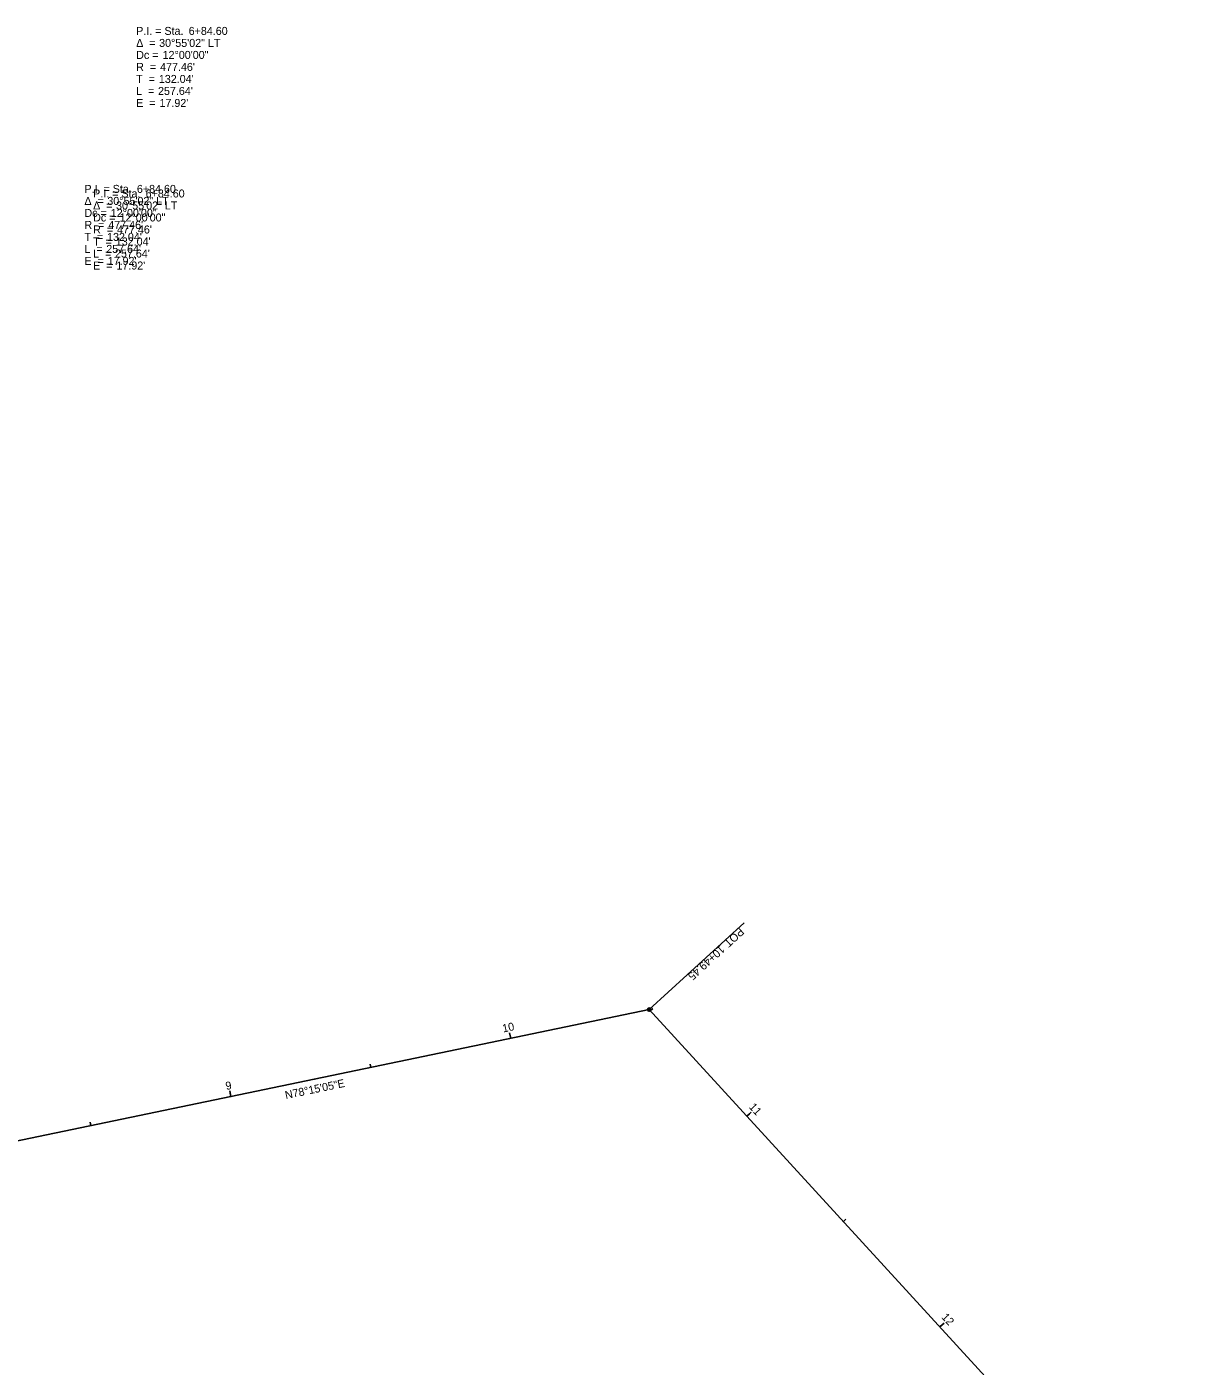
# Model space of a CAD drawing. Extents: x 2196614 to 2198263, y 660890 to 662319.
# Drawn here: x 2197020.4 to 2197426.6, y 661849.9 to 662318.5 of the extents above; entities that cross this region are included whole.
import ezdxf

# ---------------------------------------------------------------- set-up
doc = ezdxf.new("R2010")
doc.units = 0
for name, color, linetype in [('Default', 7, 'Continuous'), ('GE_X_Alignment', 7, 'Continuous'), ('GE_X_Alignment_1000_Curve_Data', 7, 'Continuous'), ('GE_X_Alignment_1000_Stations', 7, 'Continuous'), ('GE_X_Alignment_100_Curve_Data', 7, 'Continuous'), ('GE_X_Alignment_100_Stations', 7, 'Continuous'), ('GE_X_Alignment_500_Curve_Data', 7, 'Continuous'), ('GE_X_Alignment_500_Stations', 7, 'Continuous')]:
    doc.layers.add(name, color=color, linetype=linetype)

msp = doc.modelspace()

# ---------------------------------------------------------------- linework, layer by layer
at = {"layer": 'Default'}
for centre in [(2197238.07, 661974.69), (2197238.07, 661974.69), (2197238.07, 661974.69), (2197189.65, 661964.62), (2197189.65, 661964.62), (2197189.65, 661964.62), (2197120.95, 661950.33), (2197120.95, 661950.33), (2197120.95, 661950.33), (2197120.95, 661950.33), (2197120.95, 661950.33), (2197120.95, 661950.33), (2197091.75, 661944.25), (2197272.21, 661937.41), (2197339.74, 661863.66)]:
    msp.add_circle(centre, 0.0000833, dxfattribs=at)
at = {"layer": 'GE_X_Alignment'}
for p, q in [((2197003.84, 661925.97), (2197238.07, 661974.69)), ((2197238.07, 661974.69), (2197781.39, 661381.34))]:
    msp.add_line(p, q, dxfattribs=at)
at = {"layer": 'GE_X_Alignment_1000_Stations'}
for p, q in [((2197238.07, 661974.69), (2197271.26, 662005.08)), ((2197189.65, 661964.62), (2197189.25, 661966.57))]:
    msp.add_line(p, q, dxfattribs=at)
msp.add_circle((2197238.07, 661974.69), 0.6, dxfattribs=at)
at = {"layer": 'GE_X_Alignment_100_Stations'}
for p, q in [((2197238.07, 661974.69), (2197271.26, 662005.08)), ((2197238.44, 661974.28), (2197239.33, 661975.09)), ((2197189.65, 661964.62), (2197189.25, 661966.57)), ((2197140.7, 661954.43), (2197140.46, 661955.61)), ((2197091.75, 661944.25), (2197091.34, 661946.21)), ((2197272.21, 661937.41), (2197273.68, 661938.76)), ((2197042.8, 661934.07), (2197042.55, 661935.25)), ((2197305.97, 661900.53), (2197306.86, 661901.34)), ((2197339.74, 661863.66), (2197341.22, 661865.01))]:
    msp.add_line(p, q, dxfattribs=at)
msp.add_circle((2197238.07, 661974.69), 0.6, dxfattribs=at)
at = {"layer": 'GE_X_Alignment_500_Stations'}
for p, q in [((2197238.07, 661974.69), (2197271.26, 662005.08)), ((2197189.65, 661964.62), (2197189.25, 661966.57)), ((2197091.75, 661944.25), (2197091.51, 661945.43)), ((2197272.21, 661937.41), (2197273.09, 661938.22)), ((2197339.74, 661863.66), (2197340.63, 661864.47))]:
    msp.add_line(p, q, dxfattribs=at)
msp.add_circle((2197238.07, 661974.69), 0.6, dxfattribs=at)

# ---------------------------------------------------------------- texts
at = {"layer": 'GE_X_Alignment_1000_Curve_Data'}
for s, p in [('P.I. = Sta. ', (2197058.62, 662315.66)), ('6+84.60', (2197076.98, 662315.66)), ('Δ  = ', (2197058.62, 662311.46)), ('30°55\'02" LT', (2197066.64, 662311.46)), ('Dc = ', (2197058.62, 662307.26)), ('12°00\'00"', (2197067.86, 662307.26)), ('R  = ', (2197058.62, 662303.06)), ("132.04'", (2197066.55, 662298.86)), ("477.46'", (2197066.98, 662303.06)), ('T  = ', (2197058.62, 662298.86)), ('L  = ', (2197058.62, 662294.66)), ("257.64'", (2197066.26, 662294.66)), ('E  = ', (2197058.62, 662290.46)), ("17.92'", (2197066.77, 662290.46))]:
    msp.add_text(s, height=2.8, dxfattribs=at).set_placement(p)
at = {"layer": 'GE_X_Alignment_1000_Stations'}
for s, rotation, p in [('POT', 222.4797, (2197269.67, 662003.56)), ('10+49.45', 222.4797, (2197262.94, 661997.39)), ('10', 11.7486, (2197186.99, 661966.66)), ('N78°15\'05"E', 11.7486, (2197110.98, 661943.35))]:
    msp.add_text(s, height=2.8, rotation=rotation, dxfattribs=at).set_placement(p)
at = {"layer": 'GE_X_Alignment_100_Curve_Data'}
for s, p in [('P.I. = Sta. ', (2197040.51, 662260.39)), ('6+84.60', (2197058.87, 662260.39)), ('Δ  = ', (2197040.51, 662256.19)), ('30°55\'02" LT', (2197048.53, 662256.19)), ('Dc = ', (2197040.51, 662251.99)), ('R  = ', (2197040.51, 662247.79)), ("477.46'", (2197048.87, 662247.79)), ('12°00\'00"', (2197049.74, 662251.99)), ('T  = ', (2197040.51, 662243.59)), ("132.04'", (2197048.44, 662243.59)), ('L  = ', (2197040.51, 662239.39)), ("257.64'", (2197048.15, 662239.39)), ('E  = ', (2197040.51, 662235.19)), ("17.92'", (2197048.66, 662235.19))]:
    msp.add_text(s, height=2.8, dxfattribs=at).set_placement(p)
at = {"layer": 'GE_X_Alignment_100_Stations'}
for s, rotation, p in [('POT', 222.4797, (2197269.67, 662003.56)), ('10+49.45', 222.4797, (2197262.94, 661997.39)), ('10', 11.7486, (2197186.99, 661966.66)), ('N78°15\'05"E', 11.7486, (2197110.98, 661943.35)), ('9', 11.7486, (2197090.18, 661946.53)), ('11', 312.4797, (2197272.78, 661940.48)), ('12', 312.4797, (2197340.11, 661866.96))]:
    msp.add_text(s, height=2.8, rotation=rotation, dxfattribs=at).set_placement(p)
at = {"layer": 'GE_X_Alignment_500_Curve_Data'}
for s, p in [('P.I. = Sta. ', (2197043.56, 662258.79)), ('6+84.60', (2197061.93, 662258.79)), ('Δ  = ', (2197043.56, 662254.59)), ('30°55\'02" LT', (2197051.58, 662254.59)), ('Dc = ', (2197043.56, 662250.39)), ('12°00\'00"', (2197052.8, 662250.39)), ('R  = ', (2197043.56, 662246.19)), ("477.46'", (2197051.93, 662246.19)), ('T  = ', (2197043.56, 662241.99)), ("132.04'", (2197051.49, 662241.99)), ('L  = ', (2197043.56, 662237.79)), ('E  = ', (2197043.56, 662233.59)), ("257.64'", (2197051.21, 662237.79)), ("17.92'", (2197051.71, 662233.59))]:
    msp.add_text(s, height=2.8, dxfattribs=at).set_placement(p)
at = {"layer": 'GE_X_Alignment_500_Stations'}
for s, rotation, p in [('POT', 222.4797, (2197269.67, 662003.56)), ('10+49.45', 222.4797, (2197262.94, 661997.39)), ('10', 11.7486, (2197186.99, 661966.66)), ('N78°15\'05"E', 11.7486, (2197110.98, 661943.35))]:
    msp.add_text(s, height=2.8, rotation=rotation, dxfattribs=at).set_placement(p)

doc.saveas('drawing.dxf')
